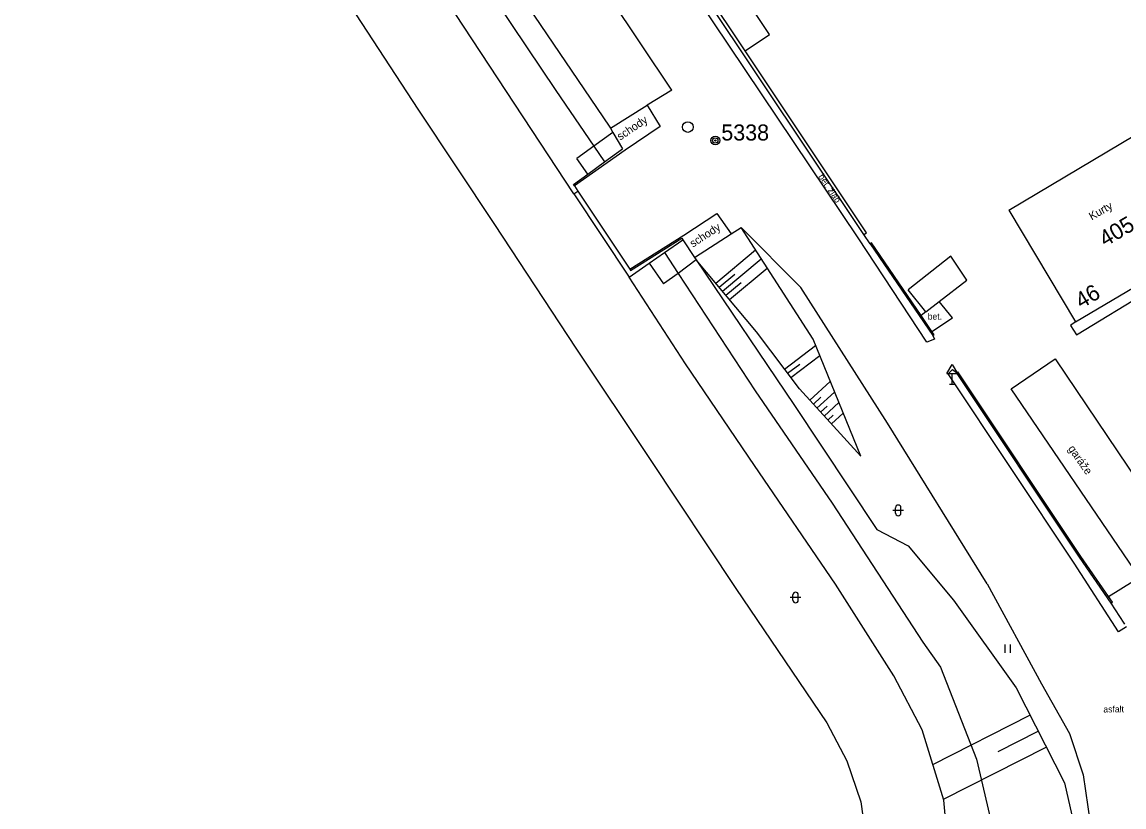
# Model space of a CAD drawing. Extents: x -493753 to -49290, y -1127285 to -112654.
# Drawn here: x -493092.6 to -492989.6, y -1126839.6 to -1126766.2 of the extents above; entities that cross this region are included whole.
import ezdxf

# ---------------------------------------------------------------- set-up
doc = ezdxf.new("R2010")
doc.units = 0
for name, color, linetype in [('Vrstva 10', 7, 'Continuous'), ('Vrstva 11', 7, 'Continuous'), ('Vrstva 14', 7, 'Continuous'), ('Vrstva 15', 7, 'Continuous'), ('Vrstva 27', 7, 'Continuous'), ('Vrstva 28', 7, 'Continuous'), ('Vrstva 34', 7, 'Continuous'), ('Vrstva 36', 7, 'Continuous'), ('Vrstva 40', 7, 'Continuous'), ('Vrstva 41', 7, 'Continuous'), ('Vrstva 42', 7, 'Continuous'), ('Vrstva 43', 7, 'Continuous'), ('Vrstva 44', 7, 'Continuous'), ('Vrstva 5', 7, 'Continuous'), ('Vrstva 63', 7, 'Continuous'), ('Vrstva 7', 7, 'Continuous'), ('Vrstva 8', 7, 'Continuous')]:
    doc.layers.add(name, color=color, linetype=linetype)

msp = doc.modelspace()

# ---------------------------------------------------------------- linework, layer by layer
at = {"layer": 'Vrstva 10'}
for p, q in [((-493031.81, -1126772.61), (-493059.34, -1126731.33)), ((-493031.81, -1126772.61), (-493034.11, -1126774.02)), ((-493037.56, -1126776.16), (-493034.11, -1126774.02)), ((-493034.11, -1126774.02), (-493032.91, -1126776.01)), ((-493032.91, -1126776.01), (-493036.17, -1126778.2)), ((-493036.17, -1126778.2), (-493040.92, -1126781.56)), ((-493030.7, -1126786.15), (-493027.6, -1126784.13)), ((-493027.6, -1126784.13), (-493026.28, -1126786.05)), ((-493026.28, -1126786.05), (-493025.35, -1126785.46)), ((-493025.35, -1126785.46), (-493019.77, -1126791.06)), ((-493035.75, -1126789.35), (-493030.7, -1126786.15)), ((-493029.69, -1126788.25), (-493026.28, -1126786.05)), ((-493007.97, -1126796.17), (-493014.41, -1126786.42)), ((-492994, -1126795.48), (-492979.48, -1126786.63)), ((-493011.66, -1126803.75), (-493019.77, -1126791.06)), ((-493005.59, -1126793.91), (-493006.82, -1126792.37)), ((-493008.08, -1126793.34), (-493008.53, -1126793.67)), ((-493007.51, -1126795.17), (-493005.59, -1126793.91)), ((-492994.08, -1126794.28), (-492994.57, -1126794.61)), ((-492994.57, -1126794.61), (-492994, -1126795.48)), ((-493007.26, -1126795.89), (-493007.97, -1126796.17)), ((-493007.42, -1126795.56), (-493007.26, -1126795.89)), ((-493005.98, -1126799.14), (-493005.59, -1126798.72)), ((-493005.59, -1126798.72), (-493005.2, -1126799.01)), ((-492994.2, -1126816.83), (-493005.98, -1126799.14)), ((-493002.35, -1126818.78), (-493011.66, -1126803.75)), ((-492990.07, -1126823.27), (-492994.2, -1126816.83)), ((-492989.32, -1126822.79), (-492990.07, -1126823.27))]:
    msp.add_line(p, q, dxfattribs=at)
for points in [[(-493002.35, -1126818.78), (-492997.26, -1126828.11), (-492994.65, -1126832.77), (-492993.37, -1126836.63), (-492992.72, -1126841.11), (-492992.46, -1126846.28), (-492992.83, -1126851.31)], [(-493085.99, -1126876.58), (-493081.54, -1126883.33), (-493079.79, -1126885.61), (-493077.75, -1126887.3), (-493072.64, -1126888.92), (-493065.43, -1126889.93), (-493057.96, -1126889.89), (-493050.65, -1126889.12), (-493043.33, -1126887.39), (-493036.34, -1126884.86), (-493029.8, -1126881.23), (-493023.7, -1126876.96), (-493017.43, -1126871), (-493013.25, -1126865.71), (-493009.57, -1126859.4), (-493006.96, -1126852.51), (-493005.82, -1126845.16), (-493006.41, -1126838.99), (-493008.43, -1126832.41), (-493011.06, -1126827.37)], [(-493017.32, -1126831.76), (-493015.46, -1126835.33), (-493014.16, -1126839.17), (-493013.55, -1126843.39), (-493013.79, -1126848.08), (-493014.89, -1126852.57), (-493016.56, -1126856.46), (-493019.32, -1126860.87), (-493022.85, -1126865.49), (-493026.58, -1126869.39), (-493031.35, -1126873.26), (-493036.81, -1126876.59), (-493049.4, -1126857.93), (-493052.68, -1126860.02), (-493040.48, -1126878.26), (-493046.94, -1126880.46), (-493052.83, -1126881.59), (-493057.83, -1126881.81), (-493063.35, -1126881.01), (-493067.77, -1126879.49), (-493071.22, -1126877.5), (-493074.32, -1126874.92), (-493076.98, -1126871.98), (-493078.63, -1126869.64)]]:
    msp.add_lwpolyline(points, dxfattribs=at)
at = {"layer": 'Vrstva 11'}
for p, q in [((-493014.41, -1126786.42), (-493054.09, -1126727.16)), ((-493062.89, -1126763.13), (-493055.56, -1126774.39)), ((-493055.56, -1126774.39), (-493048.39, -1126785.17)), ((-493048.39, -1126785.17), (-493040.8, -1126796.72)), ((-493031.22, -1126789.74), (-493024.04, -1126800.73)), ((-493040.8, -1126796.72), (-493033.89, -1126807.06)), ((-493024.04, -1126800.73), (-493016.82, -1126811.24)), ((-493033.89, -1126807.06), (-493025.83, -1126819.2)), ((-493016.82, -1126811.24), (-493008.37, -1126824.22)), ((-493025.83, -1126819.2), (-493017.32, -1126831.76)), ((-493008.37, -1126824.22), (-493006.72, -1126826.55)), ((-493006.72, -1126826.55), (-493003.33, -1126835.17)), ((-493003.33, -1126835.17), (-493002.12, -1126840.36))]:
    msp.add_line(p, q, dxfattribs=at)
for points in [[(-493092.44, -1126727.13), (-493088.09, -1126727.43), (-493085.51, -1126727.72), (-493082.46, -1126728.7), (-493080.08, -1126729.47), (-493077.26, -1126730.35), (-493074.44, -1126731.8), (-493071.43, -1126733.51), (-493068.91, -1126735.4), (-493067.45, -1126736.71), (-493065.46, -1126739.29), (-493062.16, -1126743.85), (-493057.18, -1126751.41), (-493049.55, -1126762.34), (-493042.66, -1126772.62), (-493039.1, -1126777.85)], [(-493040.97, -1126782.3), (-493054.4, -1126761.85), (-493067.3, -1126742.3), (-493069.82, -1126739.58), (-493075.57, -1126735.12), (-493077.5, -1126734.1), (-493082.15, -1126732.23), (-493088.54, -1126730.74), (-493090.61, -1126730.61), (-493098.93, -1126730.61), (-493105.56, -1126732.16), (-493111.69, -1126734.49), (-493113.63, -1126735.33), (-493117.31, -1126737.4), (-493120.54, -1126739.27), (-493125, -1126742.02)], [(-493022.69, -1126767.4), (-493041.51, -1126739.02)], [(-493024.97, -1126768.92), (-493022.69, -1126767.4)], [(-493037.32, -1126776.57), (-493039.1, -1126777.85)], [(-493039.1, -1126777.85), (-493040.7, -1126779)], [(-493039.1, -1126777.85), (-493038.1, -1126779.31)], [(-493039.66, -1126780.45), (-493040.7, -1126779)], [(-493040.97, -1126782.3), (-493040.6, -1126782.04)], [(-493040.97, -1126782.3), (-493035.8, -1126790.09)], [(-493032.49, -1126787.79), (-493030.79, -1126786.6)], [(-493035.8, -1126790.09), (-493033.93, -1126788.79)], [(-493033.93, -1126788.79), (-493032.49, -1126787.79)], [(-493033.93, -1126788.79), (-493032.59, -1126790.7)], [(-493032.49, -1126787.79), (-493031.22, -1126789.74)], [(-493029.53, -1126788.46), (-493031.22, -1126789.74)], [(-493031.22, -1126789.74), (-493032.59, -1126790.7)], [(-493024.1, -1126807.69), (-493030.55, -1126798.2), (-493035.8, -1126790.09)], [(-493011.06, -1126827.37), (-493016.53, -1126818.81), (-493024.1, -1126807.69)], [(-492991, -1126819.96), (-492986.65, -1126817.24)]]:
    msp.add_lwpolyline(points, dxfattribs=at)
at = {"layer": 'Vrstva 14'}
for p, q in [((-493018.62, -1126795.9), (-493025.35, -1126785.46)), ((-493023.92, -1126795.21), (-493029.53, -1126788.46)), ((-493019.88, -1126800.55), (-493023.92, -1126795.21)), ((-493014.16, -1126806.84), (-493018.62, -1126795.9)), ((-493014.16, -1126806.84), (-493019.88, -1126800.55))]:
    msp.add_line(p, q, dxfattribs=at)
at = {"layer": 'Vrstva 15'}
for p, q in [((-493027.72, -1126790.64), (-493024.01, -1126787.55)), ((-493027.08, -1126791.4), (-493023.46, -1126788.39)), ((-493027.4, -1126791.02), (-493025.94, -1126789.8)), ((-493026.44, -1126792.17), (-493022.91, -1126789.24)), ((-493026.76, -1126791.79), (-493025.33, -1126790.6)), ((-493021.3, -1126798.68), (-493018.39, -1126796.48)), ((-493020.69, -1126799.48), (-493018, -1126797.43)), ((-493021, -1126799.08), (-493019.87, -1126798.23)), ((-493018.93, -1126801.6), (-493017.01, -1126799.85)), ((-493018.26, -1126802.34), (-493016.61, -1126800.84)), ((-493018.59, -1126801.97), (-493017.88, -1126801.32)), ((-493017.92, -1126802.71), (-493017.31, -1126802.16)), ((-493017.58, -1126803.08), (-493016.21, -1126801.82)), ((-493017.25, -1126803.45), (-493016.75, -1126802.99)), ((-493016.91, -1126803.82), (-493015.8, -1126802.81)), ((-493007.43, -1126835.67), (-492998.35, -1126831.05)), ((-493001.33, -1126834.44), (-492997.59, -1126832.54)), ((-493006.43, -1126838.92), (-492996.83, -1126834.04))]:
    msp.add_line(p, q, dxfattribs=at)
at = {"layer": 'Vrstva 27'}
msp.add_circle((-493030.32, -1126776.05), 0.5, dxfattribs=at)
at = {"layer": 'Vrstva 28'}
msp.add_circle((-493027.76, -1126777.31), 0.25, dxfattribs=at)
at = {"layer": 'Vrstva 34'}
for p, q in [((-493006.13, -1126799.1), (-493005.63, -1126798.25)), ((-493006.13, -1126799.1), (-493005.13, -1126799.1)), ((-493005.63, -1126798.25), (-493005.13, -1126799.1)), ((-493005.63, -1126800.1), (-493005.63, -1126799.1)), ((-493005.88, -1126800.1), (-493005.38, -1126800.1))]:
    msp.add_line(p, q, dxfattribs=at)
at = {"layer": 'Vrstva 36'}
for p, q in [((-493010.16, -1126811.9), (-493011.16, -1126811.9)), ((-493010.91, -1126812.15), (-493010.91, -1126811.65)), ((-493010.41, -1126812.15), (-493010.41, -1126811.65)), ((-493019.75, -1126820.05), (-493020.75, -1126820.05)), ((-493020.5, -1126820.3), (-493020.5, -1126819.8)), ((-493020, -1126820.3), (-493020, -1126819.8)), ((-493000.65, -1126825.21), (-493000.65, -1126824.46)), ((-493000.15, -1126825.21), (-493000.15, -1126824.46))]:
    msp.add_line(p, q, dxfattribs=at)
for centre, start, end in [((-493010.66, -1126811.65), 0, 180), ((-493010.66, -1126812.15), 180, 0), ((-493020.25, -1126819.8), 0, 180), ((-493020.25, -1126820.3), 180, 0)]:
    msp.add_arc(centre, 0.25, start, end, dxfattribs=at)
at = {"layer": 'Vrstva 5'}
for p, q in [((-493000.31, -1126783.84), (-492986.7, -1126775.71)), ((-493000.31, -1126783.84), (-492994.08, -1126794.28)), ((-492994.08, -1126794.28), (-492980.38, -1126786.1)), ((-493005.74, -1126788.12), (-493009.72, -1126791.27)), ((-493004.25, -1126790.38), (-493005.74, -1126788.12)), ((-493008.08, -1126793.34), (-493009.72, -1126791.27)), ((-493000.09, -1126800.53), (-492995.98, -1126797.74)), ((-492995.98, -1126797.74), (-492984.57, -1126814.7)), ((-492988.62, -1126817.43), (-493000.09, -1126800.53))]:
    msp.add_line(p, q, dxfattribs=at)
msp.add_lwpolyline([(-493008.08, -1126793.34), (-493006.82, -1126792.37), (-493004.25, -1126790.38)], dxfattribs=at)
at = {"layer": 'Vrstva 63'}
for radius in [0.412, 0.05]:
    msp.add_circle((-493027.75, -1126777.31), radius, dxfattribs=at)
at = {"layer": 'Vrstva 7'}
for p, q in [((-493013.87, -1126786.1), (-493053.63, -1126726.5)), ((-493058.32, -1126745.47), (-493037.67, -1126775.96)), ((-493040.92, -1126781.56), (-493041.01, -1126781.44)), ((-493035.67, -1126789.48), (-493030.89, -1126786.45)), ((-493013.87, -1126786.1), (-493013.62, -1126785.93)), ((-493035.75, -1126789.35), (-493035.67, -1126789.48)), ((-493007.42, -1126795.56), (-493007.3, -1126795.48)), ((-493005.2, -1126799.01), (-493005.08, -1126798.93)), ((-492993.72, -1126816.29), (-493005.2, -1126799.01)), ((-492993.6, -1126816.2), (-493005.08, -1126798.93)), ((-493020.41, -1126802.01), (-493012.66, -1126813.69)), ((-493012.66, -1126813.69), (-493009.72, -1126815.21)), ((-493009.72, -1126815.21), (-493005.5, -1126820.31)), ((-492990.75, -1126820.58), (-492993.72, -1126816.29)), ((-492990.75, -1126820.58), (-492990.63, -1126820.49))]:
    msp.add_line(p, q, dxfattribs=at)
for points in [[(-493013.62, -1126785.93), (-493024.97, -1126768.92), (-493043.87, -1126740.59), (-493053.13, -1126726.71), (-493053.38, -1126726.33)], [(-493041.01, -1126781.44), (-493039.66, -1126780.45), (-493038.1, -1126779.31), (-493036.43, -1126778.09)], [(-493013.16, -1126786.89), (-493013.28, -1126786.97)], [(-493013.28, -1126786.97), (-493007.42, -1126795.56)], [(-493007.3, -1126795.48), (-493007.51, -1126795.17), (-493008.53, -1126793.67), (-493013.16, -1126786.89)], [(-493029.53, -1126788.46), (-493020.41, -1126802.01)], [(-492990.63, -1126820.49), (-492991, -1126819.96), (-492993.6, -1126816.2)], [(-493005.5, -1126820.31), (-492999.65, -1126828.49), (-492995.12, -1126837.39), (-492992.91, -1126847.15), (-492992.83, -1126851.31), (-492992.72, -1126857.16), (-492992.76, -1126857.32)]]:
    msp.add_lwpolyline(points, dxfattribs=at)
at = {"layer": 'Vrstva 8'}
for p, q in [((-493037.67, -1126775.96), (-493037.56, -1126776.16)), ((-493013.28, -1126786.97), (-493013.87, -1126786.1)), ((-493029.69, -1126788.25), (-493029.53, -1126788.46))]:
    msp.add_line(p, q, dxfattribs=at)
for points in [[(-493037.56, -1126776.16), (-493037.32, -1126776.57), (-493036.43, -1126778.09)], [(-493040.92, -1126781.56), (-493040.6, -1126782.04), (-493035.75, -1126789.35)], [(-493030.89, -1126786.45), (-493030.79, -1126786.6), (-493029.69, -1126788.25)], [(-492989.48, -1126822.54), (-492989.55, -1126822.44), (-492990.75, -1126820.58)]]:
    msp.add_lwpolyline(points, dxfattribs=at)

# ---------------------------------------------------------------- texts
at = {"layer": 'Vrstva 40'}
for s, rotation, p in [('bet. žlab', 303.80593, (-493018.149, -1126780.688)), ('asfalt', 0.63407, (-492991.483, -1126830.803))]:
    msp.add_text(s, height=0.6, rotation=rotation, dxfattribs=at).set_placement(p)
msp.add_text('bet.', height=0.6, dxfattribs=at).set_placement((-493007.907, -1126794.06))
at = {"layer": 'Vrstva 41'}
for s, rotation, p in [('Kurty', 29.76777, (-492992.576, -1126784.791)), ('garáže', 304.92535, (-492994.822, -1126806.133))]:
    msp.add_text(s, height=0.75, rotation=rotation, dxfattribs=at).set_placement(p)
at = {"layer": 'Vrstva 42'}
for rotation, p in [(33.89238, (-493036.641, -1126777.328)), (33.08878, (-493029.845, -1126787.336))]:
    msp.add_text('schody', height=0.75, rotation=rotation, dxfattribs=at).set_placement(p)
at = {"layer": 'Vrstva 43'}
msp.add_text('405', height=1.5, rotation=30.84059, dxfattribs=at).set_placement((-492991.309, -1126787.295))
at = {"layer": 'Vrstva 44'}
msp.add_text('46', height=1.5, rotation=30.84059, dxfattribs=at).set_placement((-492993.55, -1126793.086))
at = {"layer": 'Vrstva 63'}
msp.add_text(' 5338', height=1.5, dxfattribs=at).set_placement((-493027.75, -1126777.31))

doc.saveas('drawing.dxf')
